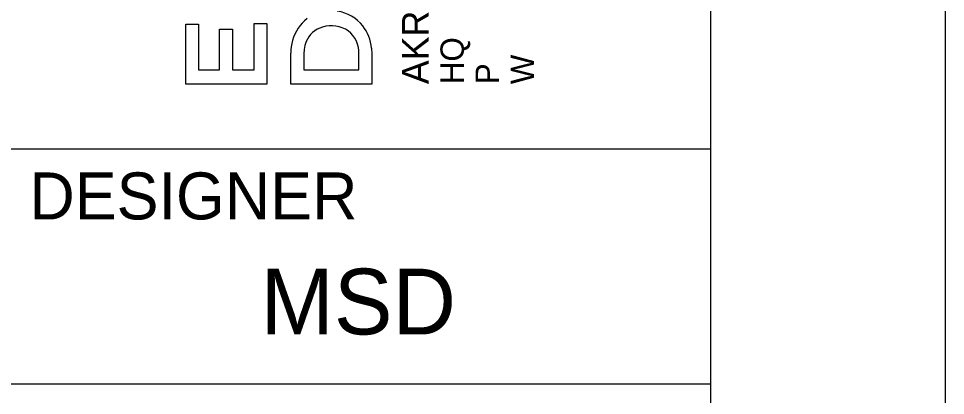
# Model space of a CAD drawing. Extents: x -1.6 to 34, y 0 to 22.
# Drawn here: x 32.027 to 34, y 2.475 to 3.278 of the extents above; entities that cross this region are included whole.
import ezdxf

# ---------------------------------------------------------------- set-up
doc = ezdxf.new("R2010")
doc.units = 0
for name, color, linetype in [('SH_Border', 7, 'Continuous'), ('SH_Cut_Line', 7, 'Continuous'), ('SH_Data', 7, 'Continuous')]:
    doc.layers.add(name, color=color, linetype=linetype)

msp = doc.modelspace()

# ---------------------------------------------------------------- linework, layer by layer
at = {"layer": 'SH_Border'}
for p, q in [((32, 3), (33.5, 3)), ((32, 2.5), (33.5, 2.5))]:
    msp.add_line(p, q, dxfattribs=at)
msp.add_lwpolyline([(1.5, 21.5), (33.5, 21.5), (33.5, 0.5), (1.5, 0.5)], close=True, dxfattribs=at)
at = {"layer": 'SH_Cut_Line'}
msp.add_lwpolyline([(0, 0), (34, 0), (34, 22), (0, 22)], close=True, dxfattribs=at)
at = {"layer": 'SH_Data'}
for p, q in [((32.383, 3.1379), (32.383, 3.266)), ((32.383, 3.266), (32.4101, 3.266)), ((32.4101, 3.266), (32.4101, 3.1683)), ((32.5286, 3.1683), (32.5286, 3.2672)), ((32.5286, 3.2672), (32.5557, 3.2672)), ((32.5557, 3.2672), (32.5557, 3.1379)), ((32.455, 3.1683), (32.455, 3.2549)), ((32.455, 3.2549), (32.4822, 3.2549)), ((32.4822, 3.2549), (32.4822, 3.1683)), ((32.6064, 3.138), (32.6064, 3.204)), ((32.6347, 3.2118), (32.6341, 3.2023)), ((32.6341, 3.2023), (32.6341, 3.1684)), ((32.7515, 3.1683), (32.7515, 3.2024)), ((32.7785, 3.215), (32.7792, 3.2021)), ((32.7792, 3.2021), (32.7792, 3.138)), ((32.4101, 3.1683), (32.455, 3.1683)), ((32.4822, 3.1683), (32.5286, 3.1683)), ((32.6341, 3.1684), (32.7515, 3.1683)), ((32.5557, 3.1379), (32.383, 3.1379)), ((32.7792, 3.138), (32.6064, 3.138))]:
    msp.add_line(p, q, dxfattribs=at)
msp.add_lwpolyline([(32.383, 3.1379), (32.383, 3.266), (32.4101, 3.266), (32.4101, 3.1683), (32.455, 3.1683), (32.455, 3.2549), (32.4822, 3.2549), (32.4822, 3.1683), (32.5286, 3.1683), (32.5286, 3.2672), (32.5557, 3.2672), (32.5557, 3.1379)], close=True, dxfattribs=at)
for points in [[(32.7785, 3.215), (32.7792, 3.2021), (32.7792, 3.138), (32.6064, 3.138)], [(32.6064, 3.138), (32.6064, 3.204)], [(32.6347, 3.2118), (32.6341, 3.2023), (32.6341, 3.1684), (32.7515, 3.1683), (32.7515, 3.2024)]]:
    msp.add_lwpolyline(points, dxfattribs=at)
for centre, radius, start, end in [((32.6939, 3.2089), 0.0865, 127.2362, 165.148), ((32.6939, 3.2089), 0.0865, 127.2362, 165.148), ((32.6946, 3.2113), 0.0827, 37.8521, 82.402), ((32.6946, 3.2113), 0.0827, 37.8521, 82.402), ((32.6889, 3.2078), 0.054, 106.1881, 157.3861), ((32.6889, 3.2078), 0.054, 106.1881, 157.3861), ((32.6928, 3.1986), 0.0639, 55.6727, 107.2093), ((32.6928, 3.1986), 0.0639, 55.6727, 107.2093), ((32.6859, 3.2057), 0.0931, 5.7333, 37.304), ((32.6859, 3.2057), 0.0931, 5.7333, 37.304), ((32.6929, 3.205), 0.0587, 357.4662, 52.2665), ((32.6929, 3.205), 0.0587, 357.4662, 52.2665), ((32.7143, 3.2028), 0.1078, 164.7861, 179.3704), ((32.7143, 3.2028), 0.1078, 164.7861, 179.3704), ((32.6983, 3.2039), 0.0641, 157.3571, 172.9275), ((32.6983, 3.2039), 0.0641, 157.3571, 172.9275)]:
    msp.add_arc(centre, radius, start, end, dxfattribs=at)

# ---------------------------------------------------------------- texts
for s, height, p in [('AKRON / CLEVELAND / COLUMBUS', 0.056969, (32.9001, 3.138)), ('HQ ', 0.04985, (32.9749, 3.138)), ('W', 0.0498, (33.1244, 3.138)), ('P', 0.0498, (33.0497, 3.138))]:
    msp.add_text(s, height=height, rotation=90, dxfattribs=at).set_placement(p)
for s, height, p in [('DESIGNER', 0.1, (32.05, 2.85)), ('MSD', 0.14, (32.5422, 2.605))]:
    msp.add_text(s, height=height, dxfattribs=at).set_placement(p)

doc.saveas('drawing.dxf')
